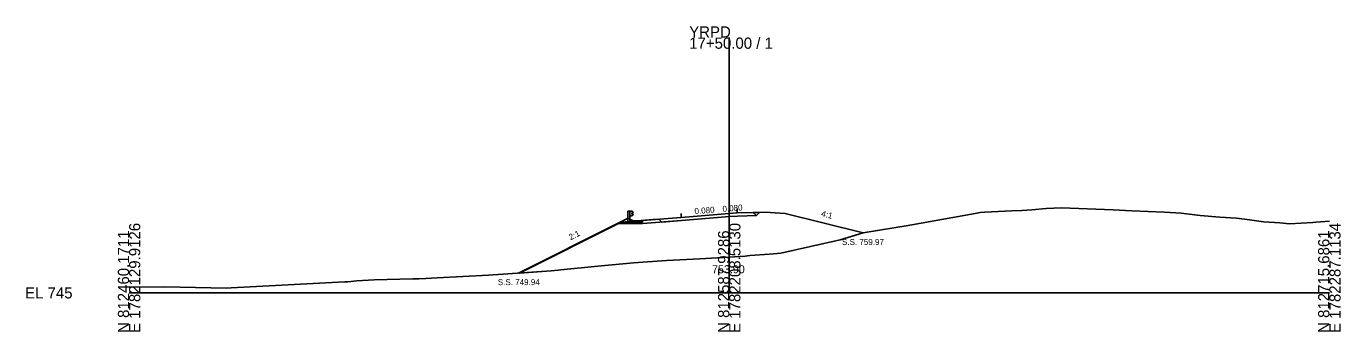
# Model space of a CAD drawing. Extents: x -26 to 1403, y -10 to 9544.
# Drawn here: x -25.7 to 302.8, y 7490.3 to 7566.6 of the extents above; entities that cross this region are included whole.
import ezdxf

# ---------------------------------------------------------------- set-up
doc = ezdxf.new("R2010")
doc.units = 0
for name, color, linetype in [('Exist Cross Section Cell', 7, 'Continuous'), ('Exist XS Center Line Elevation Label', 7, 'Continuous'), ('Exist XS Ground Line', 7, 'Continuous'), ('Prop XS Dump Level', 7, 'Continuous'), ('Prop XS Earthwork Shape', 7, 'Continuous'), ('Prop XS EOT Tick Mark', 7, 'Continuous'), ('Prop XS Finish Grade', 7, 'Continuous'), ('Prop XS Finish Grade CurbGutter', 7, 'Continuous'), ('Prop XS Finish Grade Earthwork', 7, 'Continuous'), ('Prop XS Finish Grade Paved Shoulder', 7, 'Continuous'), ('Prop XS Finish Grade Pavement', 7, 'Continuous'), ('Prop XS Guardrail', 7, 'Continuous'), ('Prop XS Pvmt Edge Slope', 7, 'Continuous'), ('Prop XS SE Text', 7, 'Continuous'), ('Prop XS Side Slope Text', 7, 'Continuous'), ('Prop XS SS Elevation Text', 7, 'Continuous'), ('Prop XS Subgrade CurbGutter', 7, 'Continuous'), ('Prop XS Subgrade Earthwork', 7, 'Continuous')]:
    doc.layers.add(name, color=color, linetype=linetype)

msp = doc.modelspace()

# ---------------------------------------------------------------- linework, layer by layer
at = {"layer": 'Exist Cross Section Cell'}
for p, q in [((150, 7500), (150, 7563.79)), ((0, 7500), (150, 7500)), ((150, 7500), (300, 7500))]:
    msp.add_line(p, q, dxfattribs=at)
at = {"layer": 'Exist XS Ground Line'}
for p, q in [((212.71, 7520.07), (213.89, 7520.15)), ((213.89, 7520.15), (217.19, 7520.34)), ((217.19, 7520.34), (220.58, 7520.47)), ((220.58, 7520.47), (223.12, 7520.56)), ((223.12, 7520.56), (225.66, 7520.78)), ((225.66, 7520.78), (229.24, 7521.11)), ((229.24, 7521.11), (233.06, 7521.26)), ((233.06, 7521.26), (245.98, 7520.74)), ((245.98, 7520.74), (250.67, 7520.52)), ((250.67, 7520.52), (258.81, 7520.15)), ((258.81, 7520.15), (261.63, 7519.98)), ((194.19, 7516.78), (195.66, 7517.02)), ((195.66, 7517.02), (211.49, 7519.81)), ((211.49, 7519.81), (212.71, 7520.07)), ((261.63, 7519.98), (262.96, 7519.9)), ((262.96, 7519.9), (267.71, 7519.37)), ((267.71, 7519.37), (272.66, 7518.95)), ((272.66, 7518.95), (276.76, 7518.67)), ((276.76, 7518.67), (279.43, 7518.32)), ((279.43, 7518.32), (280.61, 7518.14)), ((280.61, 7518.14), (283.51, 7517.74)), ((283.51, 7517.74), (287.65, 7517.48)), ((287.65, 7517.48), (290.06, 7517.21)), ((290.06, 7517.21), (295.84, 7517.58)), ((295.84, 7517.58), (296.62, 7517.65)), ((296.62, 7517.65), (297.81, 7517.74)), ((297.81, 7517.74), (300, 7517.95)), ((177.76, 7513.26), (183.49, 7514.98)), ((183.49, 7514.98), (191.62, 7516.32)), ((191.62, 7516.32), (194.19, 7516.78)), ((162.86, 7509.95), (177.76, 7513.26)), ((117.12, 7506.67), (126.09, 7507.48)), ((126.09, 7507.48), (134.3, 7508.11)), ((134.3, 7508.11), (142.69, 7508.47)), ((142.69, 7508.47), (150, 7508.9)), ((150, 7508.9), (153.96, 7509.14)), ((153.96, 7509.14), (155.14, 7509.32)), ((155.14, 7509.32), (160.11, 7509.65)), ((160.11, 7509.65), (162.86, 7509.95)), ((74.18, 7503.62), (77.03, 7503.78)), ((77.03, 7503.78), (89.84, 7504.39)), ((89.84, 7504.39), (105.52, 7505.55)), ((105.52, 7505.55), (107.24, 7505.7)), ((107.24, 7505.7), (107.88, 7505.76)), ((107.88, 7505.76), (117.12, 7506.67)), ((0, 7501.42), (8.93, 7501.53)), ((8.93, 7501.53), (24.29, 7501.19)), ((24.29, 7501.19), (25.49, 7501.26)), ((25.49, 7501.26), (53.94, 7502.76)), ((53.94, 7502.76), (54.69, 7502.79)), ((54.69, 7502.79), (56.94, 7502.98)), ((56.94, 7502.98), (61.23, 7503.3)), ((61.23, 7503.3), (70.9, 7503.49)), ((70.9, 7503.49), (72.43, 7503.48)), ((72.43, 7503.48), (74.18, 7503.62))]:
    msp.add_line(p, q, dxfattribs=at)
at = {"layer": 'Prop XS Dump Level'}
for p, q in [((138, 7518.87), (150, 7519.83)), ((150, 7519.83), (152, 7519.99))]:
    msp.add_line(p, q, dxfattribs=at)
at = {"layer": 'Prop XS Earthwork Shape'}
msp.add_lwpolyline([(133.14, 7517.69), (132.4, 7518.43), (131, 7518.31), (123, 7517.67), (97.57, 7504.96), (105.52, 7505.55), (107.24, 7505.7), (107.88, 7505.76), (117.12, 7506.67), (126.09, 7507.48), (134.3, 7508.11), (142.69, 7508.47), (150, 7508.9), (153.96, 7509.14), (155.14, 7509.32), (160.11, 7509.65), (162.86, 7509.95), (177.76, 7513.26), (183.45, 7514.97), (164, 7519.83), (159, 7520.13), (157.58, 7520.11), (156.78, 7519.3), (152.04, 7519.2), (150.06, 7519.05), (138.06, 7518.09)], close=True, dxfattribs=at)
at = {"layer": 'Prop XS EOT Tick Mark'}
for p, q in [((152, 7519.99), (152, 7520.99)), ((138, 7518.87), (138, 7519.87))]:
    msp.add_line(p, q, dxfattribs=at)
at = {"layer": 'Prop XS Finish Grade'}
for p, q in [((122.07, 7517.31), (124.73, 7518.64)), ((125.31, 7518.35), (124.73, 7518.64)), ((156, 7520.07), (157.58, 7520.11))]:
    msp.add_line(p, q, dxfattribs=at)
at = {"layer": 'Prop XS Finish Grade CurbGutter'}
for p, q in [((126, 7518.01), (125.31, 7518.35)), ((128.33, 7518.1), (126, 7518.01))]:
    msp.add_line(p, q, dxfattribs=at)
at = {"layer": 'Prop XS Finish Grade Earthwork'}
for p, q in [((157.58, 7520.11), (159, 7520.13)), ((159, 7520.13), (164, 7519.83)), ((122.07, 7517.31), (97.34, 7504.94)), ((164, 7519.83), (183.45, 7514.97))]:
    msp.add_line(p, q, dxfattribs=at)
at = {"layer": 'Prop XS Finish Grade Paved Shoulder'}
for p, q in [((138, 7518.87), (128.33, 7518.1)), ((152, 7519.99), (156, 7520.07))]:
    msp.add_line(p, q, dxfattribs=at)
at = {"layer": 'Prop XS Finish Grade Pavement'}
for p, q in [((138, 7518.87), (150, 7519.83)), ((150, 7519.83), (152, 7519.99))]:
    msp.add_line(p, q, dxfattribs=at)
at = {"layer": 'Prop XS Guardrail'}
for p, q in [((124.68, 7520.4), (125.18, 7520.4)), ((124.68, 7517.9), (124.68, 7520.4)), ((125.18, 7520.4), (125.68, 7520.4)), ((125.18, 7520.4), (125.18, 7517.9)), ((125.68, 7520.4), (125.97, 7520.2)), ((125.97, 7520.2), (126, 7520.14)), ((126, 7520.14), (125.97, 7520.08)), ((125.68, 7519.27), (125.18, 7519.27)), ((125.97, 7520.08), (125.68, 7519.88)), ((125.68, 7519.88), (125.68, 7519.79)), ((125.68, 7519.79), (125.97, 7519.59)), ((125.97, 7519.47), (125.68, 7519.27)), ((125.97, 7519.59), (126, 7519.53)), ((126, 7519.53), (125.97, 7519.47))]:
    msp.add_line(p, q, dxfattribs=at)
at = {"layer": 'Prop XS Pvmt Edge Slope'}
for p, q in [((124.31, 7517.68), (123.94, 7517.31)), ((125.31, 7517.68), (124.31, 7517.68)), ((156, 7520.07), (156.78, 7519.3))]:
    msp.add_line(p, q, dxfattribs=at)
at = {"layer": 'Prop XS Subgrade CurbGutter'}
for p, q in [((125.31, 7517.68), (125.31, 7518.35)), ((128.33, 7517.68), (125.31, 7517.68)), ((128.33, 7518.1), (128.33, 7517.68))]:
    msp.add_line(p, q, dxfattribs=at)
at = {"layer": 'Prop XS Subgrade Earthwork'}
for p, q in [((123.94, 7517.31), (122.07, 7517.31)), ((128.33, 7517.31), (123.94, 7517.31)), ((138, 7518.08), (128.33, 7517.31)), ((128.33, 7517.31), (128.33, 7517.31)), ((138.06, 7518.09), (150.06, 7519.05)), ((150.06, 7519.05), (152.04, 7519.2)), ((152.04, 7519.2), (156.78, 7519.3)), ((156.78, 7519.3), (157.58, 7520.11))]:
    msp.add_line(p, q, dxfattribs=at)

# ---------------------------------------------------------------- texts
at = {"layer": 'Exist Cross Section Cell'}
for s, p in [('YRPD', (140, 7563.79)), ('17+50.00 / 1', (140, 7560.99)), ('EL 745', (-26, 7498.6))]:
    msp.add_text(s, height=2.8, dxfattribs=at).set_placement(p)
for s, p in [('E 1782129.9126', (2.8, 7490)), ('E 1782208.5130', (152.8, 7490)), ('E 1782287.1134', (302.8, 7490)), ('N 812460.1711', (0, 7490)), ('N 812587.9286', (150, 7490)), ('N 812715.6861', (300, 7490))]:
    msp.add_text(s, height=2.8, rotation=90, dxfattribs=at).set_placement(p)
at = {"layer": 'Exist XS Center Line Elevation Label'}
msp.add_text('753.90', height=2, dxfattribs=at).set_placement((145.71, 7504.9))
at = {"layer": 'Prop XS Dump Level'}
for s, p in [('Case4', (126, 7517.87)), ('Case2', (128.33, 7518.06)), ('Case4', (164, 7519.79))]:
    msp.add_text(s, height=0.04, dxfattribs=at).set_placement(p)
at = {"layer": 'Prop XS SE Text'}
for p in [(141.38, 7519.65), (148.38, 7520.21)]:
    msp.add_text('0.080', height=1.5, rotation=4.5739, dxfattribs=at).set_placement(p)
at = {"layer": 'Prop XS Side Slope Text'}
for s, rotation, p in [('4:1', 345.9638, (172.91, 7519.15)), ('2:1', 26.5651, (110.36, 7513.13))]:
    msp.add_text(s, height=1.5, rotation=rotation, dxfattribs=at).set_placement(p)
at = {"layer": 'Prop XS SS Elevation Text'}
for s, p in [('S.S. 759.97', (178.19, 7511.97)), ('S.S. 749.94', (92.16, 7501.94))]:
    msp.add_text(s, height=1.5, dxfattribs=at).set_placement(p)

doc.saveas('drawing.dxf')
